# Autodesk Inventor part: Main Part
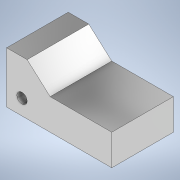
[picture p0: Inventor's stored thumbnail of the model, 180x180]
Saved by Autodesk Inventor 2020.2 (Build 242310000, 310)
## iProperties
Created: 2020-01
Part Number: Main Part
Material: Nickel-Copper Alloy 400
Document SubType Name: Modeling
Designer: thira
Density: 8.83 g/cm^3
Appearance: Chrome - Polished
Author: thira
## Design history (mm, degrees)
sketch "Sketch1"
  geometry: L1 (0, 0)-(0, 50); L2 (0, 50)-(20, 50); L3 (20, 50)-(42.361, 30); L4 (42.361, 30)-(102.361, 30); L5 (102.361, 30)-(102.361, 0); L6 (102.361, 0)-(0, 0)
  constraints: 12 end point, 2 perpendicular, 1 horizontal, 1 parallel, 1 vertical
  dimensions: "d0" = 50 distance of L1.start L1.end; "d1" = 20 distance of L1.end L2.end; "d2" = 30 distance of L2.end L3.end; "d3" = 60 distance of L3.end L4.end; "d4" = 30 distance of L4.end L5.end
extrude "Extrusion1" new body sketch "Sketch1" distance "d5" = 60; taper "d6" = 0 deg
sketch "Sketch2"
  geometry: L1 (0, 50)-(0, 0) reference; L2 (0, 0)-(102.361, 0) reference; 1 further point
  dimensions: "d7" = 15 distance from line of L1 point (15, 15); "d8" = 15 distance from line of L2 point (15, 15)
hole "Hole1" sketch "Sketch2" at (15, 15) diameter "d9" = 10; stored, may be unused: countersink angle "d13" = 90 deg, drill point angle "d15" = 118 deg; dims "d10" = 6, "d11" = 4, "d12" = 2, "d14" = 30
body "Solid1"
